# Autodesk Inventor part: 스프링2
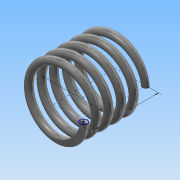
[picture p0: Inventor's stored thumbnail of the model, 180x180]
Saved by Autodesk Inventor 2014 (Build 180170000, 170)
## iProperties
Created: 2016-01
Part Number: 스프링2
Material: 스테인레스 스틸
Document SubType Name: Modeling
Designer: Administrator
Mass: 6.66796 g
Surface Area: 16.7436 cm^2
Volume: 0.825242 cm^3
Density: 8.08 g/cm^3
Appearance: 반연마
Author: Administrator
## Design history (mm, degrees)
sketch "스케치1"
  geometry: L1 (0, 0)-(8.5, 0); L2 (8.5, 0)-(8.5, 17.5); L3 (8.5, 17.5)-(0, 17.5); L4 (0, 17.5)-(0, 0); C1 r 1 at (8.5, 0)
  constraints: 8 end point, 2 parallel, 1 centre point, 1 coincident, 1 horizontal, 1 perpendicular
  dimensions: "d0" = 17.5 distance of L1.end L2.end (derived); "d1" = 2 diameter of C1; "d2" = 17 diameter of L2 L4
feature "코일1" sketch "스케치1" pitch "d3" = 10; turns "d5" = 5; dims "d4" = 17.5 (= d0), "d6" = 0, angle "d7" = 90 deg, angle "d8" = 90 deg, "d9" = 0, "d10" = 0
sketch "스케치2"
  geometry: L1 (-9.5, 0)-(-7.5, 0) reference; 1 further point
  constraints: 1 horizontal alignment
extrude "돌출1" cut sketch "스케치2" distance "d11" = 10; taper "d12" = 0 deg
node "작업 평면1"
sketch "스케치3"
  geometry: L1 (-7.5, 0)-(-9.5, 0) reference; 1 further point
  constraints: 1 horizontal alignment
extrude "돌출2" cut sketch "스케치3" stored distance "d14" = 10; taper "d15" = 0 deg
node "솔리드1"
node "절단 모서리 투영1"
node "절단 모서리 투영2"
other parameters: "d13" = 17.5 (= d0)
